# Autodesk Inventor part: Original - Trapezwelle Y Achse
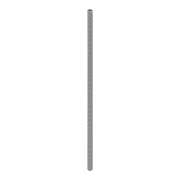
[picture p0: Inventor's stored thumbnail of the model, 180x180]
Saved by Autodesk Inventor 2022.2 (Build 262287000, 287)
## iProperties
Created: 2024-09
Part Number: Original - Trapezwelle Y Achse
Material: Acciaio inossidabile
Document SubType Name: Modeling
Designer: 18907419
Density: 8 g/cm^3
Appearance: Semilucidato
Author: 18907419
Revision Number: ANY
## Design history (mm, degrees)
feature "Schnitt-Rotation1"
node "Solido1"
